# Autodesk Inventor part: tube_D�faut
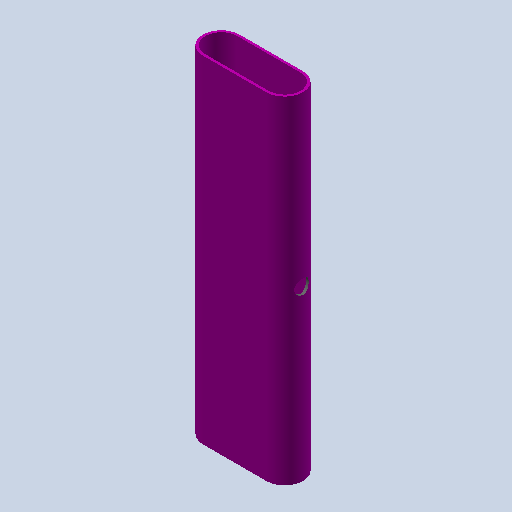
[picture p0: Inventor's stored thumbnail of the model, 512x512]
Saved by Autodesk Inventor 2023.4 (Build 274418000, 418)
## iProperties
Created: 2011-01
Part Number: tube_D�faut
Document SubType Name: Modeling
Designer: eric
Density: 1 g/cm^3
Mass: 15.2303 g
Surface Area: 270.615 cm^2
Volume: 15.2303 cm^3
Material: Générique
Appearance: 128,128,128
Author: eric
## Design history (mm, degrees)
feature "Base1"
node "Corps solides"
node "Corps surfaciques"
node "Solide1"
